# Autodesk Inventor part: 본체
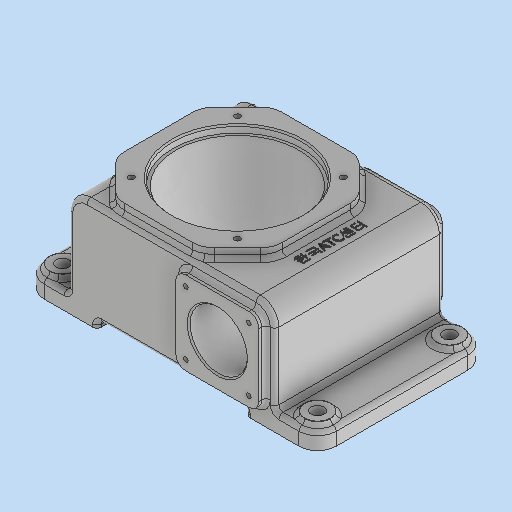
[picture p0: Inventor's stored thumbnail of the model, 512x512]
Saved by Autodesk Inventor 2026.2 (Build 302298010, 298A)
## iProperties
Created: 2026-02
Part Number: 본체
Material: 일반
Document SubType Name: Modeling
Designer: PC2-14
Density: 1 g/cm^3
Appearance: 기본값
Mass: 863.688 g
Surface Area: 1208.56 cm^2
Volume: 863.688 cm^3
Author: PC2-14
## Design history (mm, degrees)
sketch "스케치1"
  geometry: L1 (-102, 59)-(102, 59); L2 (102, 59)-(102, -59); L3 (102, -59)-(-102, -59); L4 (-102, -59)-(-102, 59); 3 further points
  constraints: 8 end point, 2 midpoint, 2 parallel, 1 horizontal, 1 horizontal alignment, 1 perpendicular, 1 vertical alignment
  dimensions: "d0" = 204 distance between parallel lines of L2 L4; "d1" = 118 distance between parallel lines of L3 L1
extrude "돌출1" new body sketch "스케치1" distance "d2" = 75; taper "d3" = 0 deg
sketch "스케치2"
  geometry: L1 (0, 0)-(204, 0) reference; L2 (50, 0)-(154, 0); L3 (154, 0)-(154, 5); L4 (154, 5)-(50, 5); L5 (50, 5)-(50, 0); 3 further points
  constraints: 8 end point, 2 parallel, 1 horizontal, 1 midpoint, 1 perpendicular, 1 point on line
  dimensions: "d4" = 52 distance from line of point (102, 0) L5; "d5" = 104 distance between parallel lines of L3 L5; "d6" = 5 distance between parallel lines of L1 L4
extrude "돌출2" cut sketch "스케치2" extent not by distance; stored distance "d7" = 75; taper "d8" = 0 deg
sketch "스케치3"
  geometry: L1 (-102, 59)-(-102, -59) reference; L2 (-102, 59)-(-72, 59); L3 (-72, 59)-(-72, -59); L4 (-72, -59)-(-102, -59); L5 (-102, -59)-(-102, 59); L6 (102, 59)-(52, 59) reference; L7 (52, -59)-(102, -59) reference; L8 (72, 59)-(102, 59); L9 (102, 59)-(102, -59); L10 (102, -59)-(72, -59); L11 (72, -59)-(72, 59); 3 further points
  constraints: 16 end point, 4 parallel, 2 horizontal, 2 perpendicular, 2 point on line
  dimensions: "d9" = 30 distance between parallel lines of L3 L1; "d10" = 30 distance between parallel lines of L9 L11
extrude "돌출3" cut sketch "스케치3" distance "d11" = 63; taper "d12" = 0 deg
sketch "스케치5"
  geometry: L1 (72, 59)-(-72, 59) reference; L2 (-102, -59)-(-102, 59) reference; C1 r 9 at (-89, 46); C2 r 9 at (-89, -46); C3 r 9 at (89, 46); C4 r 9 at (89, -46); 3 further points
  constraints: 4 centre point, 2 equal radius, 2 horizontal alignment, 2 midpoint, 2 vertical alignment
  dimensions: "d16" = 18 diameter of C1; "d17" = 18 diameter of C3; "d18" = 178 distance of C3.centre C1.centre; "d19" = 89 horizontal distance of point (0, 59) C1.centre; "d21" = 46 vertical distance of point (-102, 0) C2.centre; "d22" = 92 distance of C1.centre C2.centre
extrude "돌출4" join sketch "스케치5" distance "d23" = 3; taper "d24" = 0 deg
sketch "스케치6"
  geometry: L1 (110, 69)-(168, 69); L2 (168, 69)-(168, 11); L3 (168, 11)-(110, 11); L4 (110, 11)-(110, 69); L5 (154, 0)-(204, 0) reference; L6 (200, 15)-(182, 15) reference; 4 further points
  constraints: 8 end point, 3 midpoint, 2 parallel, 1 horizontal, 1 perpendicular
  dimensions: "d25" = 58 distance between parallel lines of L2 L4; "d26" = 58 distance between parallel lines of L1 L3; "d27" = 40 distance from line of L5 point (168, 40); "d28" = 52 horizontal distance of point (139, 11) point (191, 15)
extrude "돌출5" join sketch "스케치6" distance "d29" = 5; taper "d30" = 0 deg
sketch "스케치7"
  geometry: L1 (-43, -55)-(17, -55); L2 (42, -30)-(42, 30); L3 (17, 55)-(-43, 55); L4 (-68, 30)-(-68, -30); L5 (-68, -55)-(42, 55); L6 (42, -55)-(-68, 55); L7 (-43, -55)-(-68, -30); L8 (-68, 30)-(-43, 55); L9 (42, 30)-(17, 55); L10 (42, -30)-(17, -55); L11 (102, 59)-(102, -59) reference; 2 further points
  constraints: 20 end point, 8 point on line, 3 midpoint, 2 parallel, 1 horizontal, 1 horizontal alignment, 1 perpendicular
  dimensions: "d42" = 110 distance between parallel lines of L2 L4; "d43" = 110 distance between parallel lines of L3 L1; "d44" = 25 distance of L1.start L5.start; "d45" = 25 distance of L4.end L5.start (= d44); "d46" = 25 distance of L4.start L6.end (= d44); "d47" = 25 distance of L3.end L6.end (= d46); "d48" = 25 distance of L2.end L5.end (= d44); "d49" = 25 distance of L3.start L5.end (= d48); "d50" = 25 distance of L2.start L6.start (= d44); "d51" = 25 distance of L1.end L6.start (= d50); "d52" = 115 distance from line of point (-13, 0) L11
extrude "돌출6" join sketch "스케치7" distance "d53" = 7; taper "d54" = 0 deg
fillet "모깎기1" dims "d55" = 13
sketch "스케치8"
  geometry: L1 (43, 82)-(-17, 82) reference; L2 (13, 82)-(13, 77); L3 (13, 77)-(58, 77); L4 (58, 77)-(58, 82); L5 (58, 82)-(13, 82); 2 further points
  constraints: 8 end point, 2 perpendicular, 1 collinear, 1 midpoint, 1 vertical
  dimensions: "d56" = 5 distance between parallel lines of L3 L1; "d57" = 90 diameter of L4 L2
revolve "회전1" sketch "스케치8" stored, may be unused: angle "d58" = 90 deg
chamfer "모따기1" distance "d59" = 1; stored, may be unused: second distance "d60" = 2, angle "d61" = 45 deg
sketch "스케치9"
  geometry: L1 (58, 77)-(-32, 77) reference; L2 (13, 77)-(13, 22); L3 (13, 22)-(36.757, 22); L4 (38.879, 21.121)-(43.121, 16.879); L5 (45.243, 16)-(56, 16); L6 (56, 16)-(56, 77); L7 (13, 77)-(56, 77); L8 (-17, 75)-(43, 75) reference; A1 r 3 centre (36.757, 19) between (38.879, 21.121) and (36.757, 22); A2 r 3 centre (45.243, 19) between (43.121, 16.879) and (45.243, 16); 3 further points
  constraints: 12 end point, 5 point on line, 4 point on circle, 4 tangent, 2 centre point, 2 parallel, 2 perpendicular, 1 midpoint, 1 vertical
  dimensions: "d62" = 61 distance between parallel lines of L5 L1; "d63" = 86 diameter of L6 L2; "d64" = 45 deg angle of L2 L4; "d65" = 50 diameter of point (38, 22) L2; "d66" = 6 distance between parallel lines of L5 L3; "d76" = 3 radius of A1 (derived); "d77" = 3 radius of A2 (derived)
revolve "회전2" sketch "스케치9" stored, may be unused: angle "d67" = 90 deg
fillet "모깎기3" dims "d75" = 3
sketch "스케치11"
  geometry: L1 (36.757, 22)-(-10.757, 22) reference; L2 (13, 22)-(13, 11); L3 (13, 11)-(33, 11); L4 (33, 11)-(33, 22); L5 (13, 22)-(33, 22); 1 further point
  constraints: 8 end point, 3 perpendicular, 1 midpoint, 1 point on line, 1 vertical
  dimensions: "d78" = 11 distance between parallel lines of L3 L1; "d79" = 40 diameter of L4 L2
revolve "회전4" sketch "스케치11" stored, may be unused: angle "d80" = 90 deg
chamfer "모따기3" distance "d81" = 1; stored, may be unused: second distance "d82" = 2, angle "d83" = 45 deg
fillet "모깎기4" dims "d84" = 1.5
sketch "스케치12"
  geometry: L1 (168, 11)-(168, 69) reference; L2 (168, 69)-(110, 69) reference; C1 r 20 at (139, 40); 3 further points
  constraints: 2 midpoint, 1 centre point, 1 horizontal alignment, 1 vertical alignment
  dimensions: "d85" = 40 diameter of C1
extrude "돌출7" cut sketch "스케치12" extent not by distance; stored distance "d86" = 0; taper "d87" = 0 deg
sketch "스케치13"
  geometry: C1 r 18.5 at (-13, 0) reference; 5 further points
  constraints: 2 horizontal alignment, 2 vertical alignment
  dimensions: "d88" = 74 distance of point (24, 37) point (-50, 37); "d89" = 74 distance of point (-50, -37) point (-50, 37); "d90" = 37 vertical distance of point (0, 0) point (-50, 37); "d91" = 37 horizontal distance of C1.centre point (24, 37)
hole "구멍1" sketch "스케치13" at (-50, 37), (-50, -37), (24, -37), (24, 37) diameter "d92" = 4.134; stored, may be unused: countersink angle "d96" = 90 deg, drill point angle "d98" = 118 deg; dims "d93" = 10, "d94" = 4, "d95" = 2, "d97" = 12
sketch "스케치14"
  geometry: L1 (110, 69)-(110, 11) reference; L2 (168, 69)-(110, 69) reference; 7 further points
  constraints: 2 horizontal alignment, 2 midpoint, 2 vertical alignment
  dimensions: "d99" = 44 distance of point (161, 62) point (117, 62); "d100" = 44 distance of point (117, 18) point (117, 62); "d101" = 22 vertical distance of point (110, 40) point (117, 62); "d102" = 22 horizontal distance of point (139, 69) point (117, 62)
hole "구멍2" sketch "스케치14" at (117, 62), (161, 62), (117, 18), (161, 18) diameter "d103" = 3.242; stored, may be unused: countersink angle "d107" = 90 deg, drill point angle "d109" = 118 deg; dims "d104" = 8, "d105" = 4, "d106" = 2, "d108" = 10
chamfer "모따기4" distance "d110" = 1; stored, may be unused: second distance "d111" = 2, angle "d112" = 45 deg
chamfer "모따기5" distance "d113" = 1; stored, may be unused: second distance "d114" = 2, angle "d115" = 45 deg
sketch "스케치15"
  geometry: C1 r 9 at (0, 0) reference; C2 r 9 at (0, 92) reference; C3 r 9 at (-178, 0) reference; C4 r 9 at (-178, 92) reference; 5 further points
  constraints: 4 coincident
hole "구멍3" sketch "스케치15" at (0, 0), (0, 92), (-178, 0), (-178, 92) diameter "d116" = 9; stored, may be unused: countersink angle "d120" = 90 deg, drill point angle "d122" = 118 deg; dims "d117" = 8, "d118" = 4, "d119" = 2, "d121" = 10
fillet "모깎기5" dims "d123" = 13
fillet "모깎기6" dims "d124" = 7
fillet "모깎기7" dims "d125" = 3
fillet "모깎기8" dims "d126" = 3
fillet "모깎기9" dims "d127" = 3
fillet "모깎기10" dims "d128" = 15
fillet "모깎기11" dims "d129" = 3
fillet "모깎기12" dims "d130" = 2.9
sketch "스케치16"
  geometry: L1 (48.623, -23.864)-(48.623, 23.864); L2 (48.623, 23.864)-(55.377, 23.864); L3 (55.377, 23.864)-(55.377, -23.864); L4 (55.377, -23.864)-(48.623, -23.864); C1 r 18.5 at (-13, 0) reference; 3 further points
  constraints: 2 midpoint, 1 horizontal alignment, 2 other
  dimensions: "d131" = 65 horizontal distance of point (52, -23.864) C1.centre
feature "엠보싱1" sketch "스케치16" dims "d132" = 0.5, "d133" = 0
fillet "모깎기13" dims "d134" = 3
fillet "모깎기14" dims "d135" = 3
node "솔리드1"
mirror "미러1"
mirror "미러2"
feature "A9D066F2-1C7D-4E18-AEED-F7BC21143FA4" dims "d116" = 9, "d117" = 8, "d118" = 4, "d119" = 2, "d120" = 90 deg, "d121" = 10, "d122" = 118 deg
